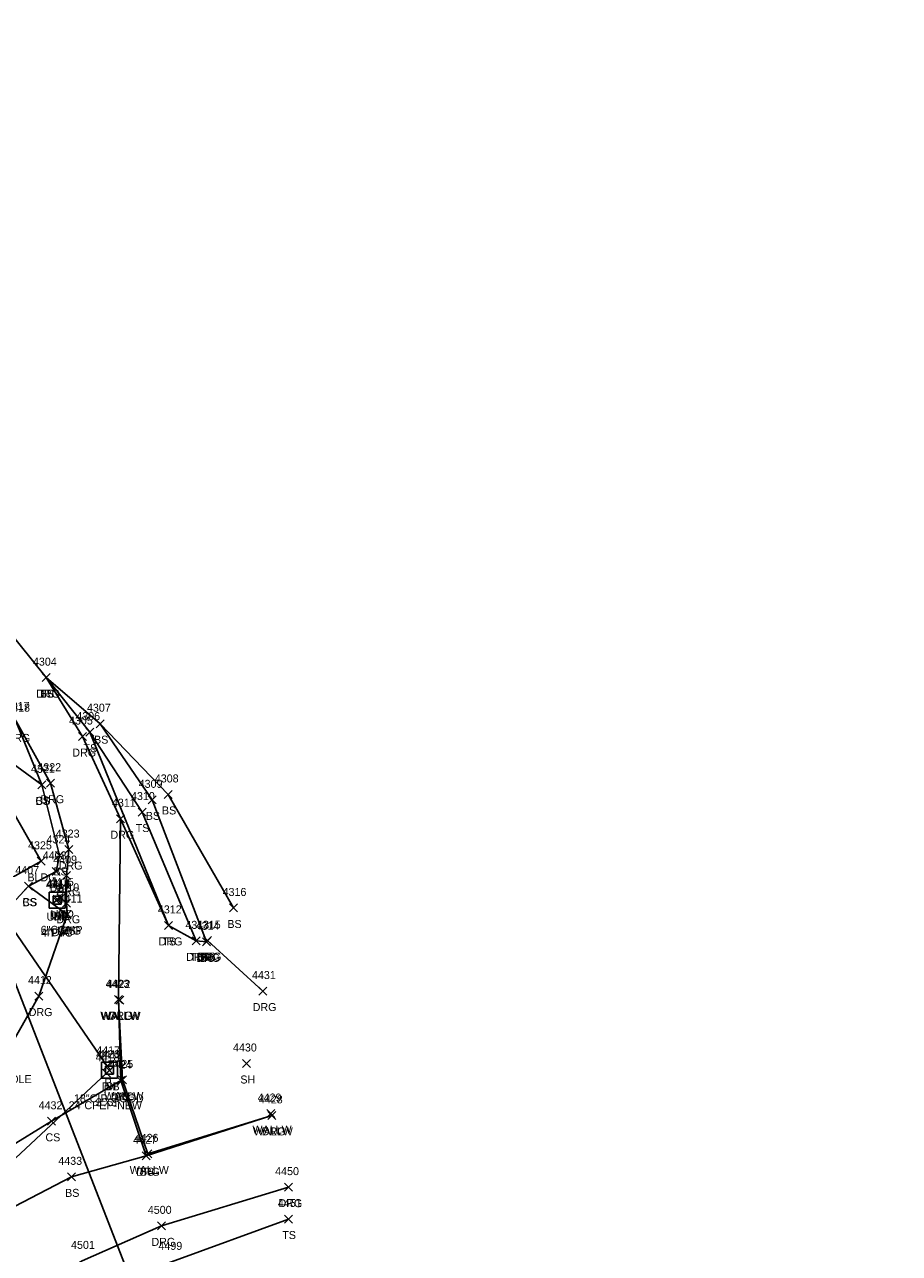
# Model space of a CAD drawing. Extents: x 49137 to 50946, y 9590 to 10709.
# Drawn here: x 50204 to 50422.7, y 10392.7 to 10699.8 of the extents above; entities that cross this region are included whole.
import ezdxf

# ---------------------------------------------------------------- set-up
doc = ezdxf.new("R2010")
doc.units = 0
for name, color, linetype in [('D_A', 7, 'Continuous'), ('D_C', 7, 'Continuous'), ('D_I', 7, 'Continuous'), ('D_TIC', 7, 'Continuous'), ('DCP', 7, 'Continuous'), ('DS', 7, 'Continuous'), ('L_A', 7, 'Continuous'), ('L_C', 7, 'Continuous'), ('L_I', 7, 'Continuous'), ('L_TIC', 7, 'Continuous'), ('LBC', 7, 'Continuous'), ('LELB', 7, 'Continuous'), ('LW', 7, 'Continuous'), ('R_A', 7, 'Continuous'), ('R_I', 7, 'Continuous'), ('R_TIC', 7, 'Continuous'), ('RDG', 7, 'Continuous')]:
    doc.layers.add(name, color=color, linetype=linetype)

msp = doc.modelspace()

# ---------------------------------------------------------------- linework, layer by layer
at = {"layer": 'D_TIC'}
for points in [[(50211.01, 10479.85), (50213.01, 10481.85)], [(50213.01, 10479.85), (50211.01, 10481.85)], [(50211.17, 10480.18), (50213.17, 10482.18)], [(50213.17, 10480.18), (50211.17, 10482.18)], [(50212.02, 10480.55), (50214.02, 10482.55)], [(50214.02, 10480.55), (50212.02, 10482.55)], [(50223.61, 10438.45), (50225.61, 10440.45)], [(50225.61, 10438.45), (50223.61, 10440.45)], [(50223.44, 10436.72), (50225.44, 10438.72)], [(50225.44, 10436.72), (50223.44, 10438.72)], [(50224.19, 10437.43), (50226.19, 10439.43)], [(50226.19, 10437.43), (50224.19, 10439.43)]]:
    msp.add_lwpolyline(points, dxfattribs=at)
at = {"layer": 'DCP'}
for points in [[(49941.69, 9827.48), (50059.34, 9808.37), (50181.4, 9733.09), (50281.74, 9743.29), (50422.72, 9892.52), (50122.34, 10663.61), (50179.93, 10552.61), (50179.64, 10394.45), (50122.34, 10285.07), (50121.56, 10284.35)], [(50173.14, 10514.39), (50224.61, 10439.45)], [(50224.44, 10437.72), (50180.22, 10396.54)]]:
    msp.add_lwpolyline(points, dxfattribs=at)
at = {"layer": 'DS'}
for p, q in [((50210.14, 10482.97), (50214.14, 10482.97)), ((50210.14, 10478.97), (50210.14, 10482.97)), ((50211.14, 10479.97), (50211.14, 10481.97)), ((50211.14, 10481.97), (50213.14, 10481.97)), ((50213.14, 10479.97), (50211.14, 10479.97)), ((50212.14, 10480.97), (50212.14, 10480.97)), ((50212.14, 10480.97), (50212.14, 10480.97)), ((50213.14, 10481.97), (50213.14, 10479.97)), ((50214.14, 10482.97), (50214.14, 10478.97)), ((50214.14, 10478.97), (50210.14, 10478.97)), ((50223.21, 10440.47), (50227.21, 10440.47)), ((50223.21, 10436.47), (50223.21, 10440.47)), ((50227.21, 10440.47), (50227.21, 10436.47)), ((50224.21, 10437.47), (50224.21, 10439.47)), ((50224.21, 10439.47), (50226.21, 10439.47)), ((50226.21, 10437.47), (50224.21, 10437.47)), ((50225.22, 10438.48), (50225.22, 10438.48)), ((50225.22, 10438.48), (50225.22, 10438.48)), ((50226.21, 10439.47), (50226.21, 10437.47)), ((50227.21, 10436.47), (50223.21, 10436.47))]:
    msp.add_line(p, q, dxfattribs=at)
at = {"layer": 'L_TIC'}
for points in [[(50208.41, 10535.57), (50210.41, 10537.57)], [(50210.41, 10535.57), (50208.41, 10537.57)], [(50208.41, 10535.57), (50210.41, 10537.57)], [(50210.41, 10535.57), (50208.41, 10537.57)], [(50221.92, 10524.07), (50223.92, 10526.07)], [(50223.92, 10524.07), (50221.92, 10526.07)], [(50221.92, 10524.07), (50223.92, 10526.07)], [(50223.92, 10524.07), (50221.92, 10526.07)], [(50219.31, 10521.95), (50221.31, 10523.95)], [(50221.31, 10521.95), (50219.31, 10523.95)], [(50219.31, 10521.95), (50221.31, 10523.95)], [(50221.31, 10521.95), (50219.31, 10523.95)], [(50207.27, 10508.79), (50209.27, 10510.79)], [(50209.27, 10508.79), (50207.27, 10510.79)], [(50207.27, 10508.79), (50209.27, 10510.79)], [(50209.27, 10508.79), (50207.27, 10510.79)], [(50238.89, 10506.39), (50240.89, 10508.39)], [(50240.89, 10506.39), (50238.89, 10508.39)], [(50234.85, 10505.04), (50236.85, 10507.04)], [(50236.85, 10505.04), (50234.85, 10507.04)], [(50232.37, 10501.99), (50234.37, 10503.99)], [(50234.37, 10501.99), (50232.37, 10503.99)], [(50211.74, 10491.15), (50213.74, 10493.15)], [(50213.74, 10491.15), (50211.74, 10493.15)], [(50207.1, 10489.68), (50209.1, 10491.68)], [(50209.1, 10489.68), (50207.1, 10491.68)], [(50207.1, 10489.68), (50209.1, 10491.68)], [(50209.1, 10489.68), (50207.1, 10491.68)], [(50210.87, 10487.15), (50212.87, 10489.15)], [(50212.87, 10487.15), (50210.87, 10489.15)], [(50210.87, 10487.15), (50212.87, 10489.15)], [(50212.87, 10487.15), (50210.87, 10489.15)], [(50204, 10483.47), (50206, 10485.47)], [(50206, 10483.47), (50204, 10485.47)], [(50204, 10483.47), (50206, 10485.47)], [(50206, 10483.47), (50204, 10485.47)], [(50255.24, 10478.02), (50257.24, 10480.02)], [(50257.24, 10478.02), (50255.24, 10480.02)], [(50213.66, 10476.36), (50215.66, 10478.36)], [(50215.66, 10476.36), (50213.66, 10478.36)], [(50239.01, 10473.66), (50241.01, 10475.66)], [(50241.01, 10473.66), (50239.01, 10475.66)], [(50245.88, 10469.8), (50247.88, 10471.8)], [(50247.88, 10469.8), (50245.88, 10471.8)], [(50248.46, 10469.56), (50250.46, 10471.56)], [(50250.46, 10469.56), (50248.46, 10471.56)], [(50248.76, 10469.86), (50250.76, 10471.86)], [(50250.76, 10469.86), (50248.76, 10471.86)], [(50226.51, 10455.11), (50228.51, 10457.11)], [(50228.51, 10455.11), (50226.51, 10457.11)], [(50226.77, 10455), (50228.77, 10457)], [(50228.77, 10455), (50226.77, 10457)], [(50258.44, 10439.16), (50260.44, 10441.16)], [(50260.44, 10439.16), (50258.44, 10441.16)], [(50227.46, 10435.05), (50229.46, 10437.05)], [(50229.46, 10435.05), (50227.46, 10437.05)], [(50227.06, 10434.89), (50229.06, 10436.89)], [(50229.06, 10434.89), (50227.06, 10436.89)], [(50264.54, 10426.65), (50266.54, 10428.65)], [(50266.54, 10426.65), (50264.54, 10428.65)], [(50264.83, 10426.19), (50266.83, 10428.19)], [(50266.83, 10426.19), (50264.83, 10428.19)], [(50209.76, 10424.71), (50211.76, 10426.71)], [(50211.76, 10424.71), (50209.76, 10426.71)], [(50233.83, 10416.58), (50235.83, 10418.58)], [(50235.83, 10416.58), (50233.83, 10418.58)], [(50233.37, 10416.11), (50235.37, 10418.11)], [(50235.37, 10416.11), (50233.37, 10418.11)], [(50214.68, 10410.83), (50216.68, 10412.83)], [(50216.68, 10410.83), (50214.68, 10412.83)], [(50269.01, 10400.29), (50271.01, 10402.29)], [(50271.01, 10400.29), (50269.01, 10402.29)]]:
    msp.add_lwpolyline(points, dxfattribs=at)
at = {"layer": 'LBC'}
for points in [[(50208.1, 10490.68), (50199.54, 10505.75), (50188.54, 10499.87), (50193.08, 10491.83), (50197.16, 10484.51)], [(50208.1, 10490.68), (50197.16, 10484.51)]]:
    msp.add_lwpolyline(points, dxfattribs=at)
at = {"layer": 'LELB'}
for points in [[(50121.04, 10673.8), (50125.72, 10663.25), (50118.76, 10654.2), (50121.52, 10635.5), (50130.84, 10628.15), (50141.37, 10625.76), (50142.8, 10621.81), (50131.45, 10616.61), (50128.86, 10614.81), (50135.94, 10599.09), (50146.92, 10581.6), (50169.4, 10551.93), (50172.24, 10543.56), (50191.94, 10521.73), (50208.27, 10509.79)], [(50121.52, 10635.5), (50126.1, 10622.98), (50139.03, 10624.1), (50139.75, 10622.38), (50131.45, 10616.61), (50139.21, 10602.48), (50154.46, 10587.74), (50176.56, 10559.26), (50177.99, 10558.38), (50179.93, 10552.61), (50184.02, 10545.02), (50202.08, 10525.08), (50208.27, 10509.79), (50212.74, 10492.15), (50211.87, 10488.15)], [(50209.41, 10536.57), (50220.31, 10522.95), (50240.01, 10474.66)], [(50209.41, 10536.57), (50222.92, 10525.07), (50239.89, 10507.39), (50256.24, 10479.02)], [(50220.31, 10522.95), (50233.37, 10502.99), (50246.88, 10470.8)], [(50222.92, 10525.07), (50235.85, 10506.04), (50249.46, 10470.56), (50249.76, 10470.86)], [(50193.08, 10491.83), (50184.77, 10485.47), (50176.86, 10484.26), (50163.55, 10486.17), (50159.26, 10479.24), (50156.56, 10465.2), (50172.98, 10448.23), (50182.56, 10448.61), (50194.13, 10450.62), (50200.1, 10459.65), (50198.7, 10477.72), (50205, 10484.47), (50211.87, 10488.15)], [(50205, 10484.47), (50214.66, 10477.36)], [(50228.06, 10435.89), (50210.76, 10425.71), (50188.5, 10412.1), (50178.8, 10406.39)], [(50234.37, 10417.11), (50215.68, 10411.83), (50195.33, 10401.24), (50187.41, 10396.19)], [(50270.01, 10401.29), (50240.73, 10390.59), (50219.39, 10384), (50208.28, 10377.18), (50194.78, 10363.54), (50184.26, 10345.55), (50178.27, 10336.12)]]:
    msp.add_lwpolyline(points, dxfattribs=at)
at = {"layer": 'LW'}
msp.add_lwpolyline([(50227.77, 10456), (50227.51, 10456.11), (50228.46, 10436.05), (50234.83, 10417.58), (50265.83, 10427.19), (50265.54, 10427.65)], dxfattribs=at)
at = {"layer": 'R_TIC'}
for points in [[(50208.41, 10535.57), (50210.41, 10537.57)], [(50210.41, 10535.57), (50208.41, 10537.57)], [(50217.43, 10520.85), (50219.43, 10522.85)], [(50219.43, 10520.85), (50217.43, 10522.85)], [(50209.44, 10509.19), (50211.44, 10511.19)], [(50211.44, 10509.19), (50209.44, 10511.19)], [(50226.96, 10500.32), (50228.96, 10502.32)], [(50228.96, 10500.32), (50226.96, 10502.32)], [(50226.96, 10500.32), (50228.96, 10502.32)], [(50228.96, 10500.32), (50226.96, 10502.32)], [(50214.05, 10492.61), (50216.05, 10494.61)], [(50216.05, 10492.61), (50214.05, 10494.61)], [(50213.49, 10486.12), (50215.49, 10488.12)], [(50215.49, 10486.12), (50213.49, 10488.12)], [(50213.47, 10479.19), (50215.47, 10481.19)], [(50215.47, 10479.19), (50213.47, 10481.19)], [(50213.66, 10476.36), (50215.66, 10478.36)], [(50215.66, 10476.36), (50213.66, 10478.36)], [(50239.01, 10473.66), (50241.01, 10475.66)], [(50241.01, 10473.66), (50239.01, 10475.66)], [(50245.88, 10469.8), (50247.88, 10471.8)], [(50247.88, 10469.8), (50245.88, 10471.8)], [(50248.46, 10469.56), (50250.46, 10471.56)], [(50250.46, 10469.56), (50248.46, 10471.56)], [(50248.76, 10469.86), (50250.76, 10471.86)], [(50250.76, 10469.86), (50248.76, 10471.86)], [(50262.53, 10457.26), (50264.53, 10459.26)], [(50264.53, 10457.26), (50262.53, 10459.26)], [(50206.53, 10456), (50208.53, 10458)], [(50208.53, 10456), (50206.53, 10458)], [(50206.53, 10456), (50208.53, 10458)], [(50208.53, 10456), (50206.53, 10458)], [(50226.51, 10455.11), (50228.51, 10457.11)], [(50228.51, 10455.11), (50226.51, 10457.11)], [(50227.06, 10434.89), (50229.06, 10436.89)], [(50229.06, 10434.89), (50227.06, 10436.89)], [(50264.83, 10426.19), (50266.83, 10428.19)], [(50266.83, 10426.19), (50264.83, 10428.19)], [(50233.37, 10416.11), (50235.37, 10418.11)], [(50235.37, 10416.11), (50233.37, 10418.11)], [(50268.98, 10408.26), (50270.98, 10410.26)], [(50270.98, 10408.26), (50268.98, 10410.26)], [(50237.23, 10398.59), (50239.23, 10400.59)], [(50239.23, 10398.59), (50237.23, 10400.59)]]:
    msp.add_lwpolyline(points, dxfattribs=at)
at = {"layer": 'RDG'}
for points in [[(50119.02, 10699.76), (50135.14, 10671.06), (50153.64, 10632.53), (50170.9, 10598.36), (50195.96, 10553.2), (50209.41, 10536.57), (50218.43, 10521.85), (50227.96, 10501.32), (50227.51, 10456.11), (50228.06, 10435.89), (50234.37, 10417.11), (50265.83, 10427.19)], [(50110.8, 10693.82), (50121.04, 10673.8), (50126.58, 10664.65), (50145.31, 10626.1), (50162.07, 10592.03), (50186.9, 10549.34), (50201.97, 10525.51), (50210.44, 10510.19), (50215.05, 10493.61), (50214.49, 10487.12), (50214.47, 10480.19), (50214.66, 10477.36), (50207.53, 10457)], [(50095.25, 10547.5), (50093.45, 10565.17), (50103.93, 10565.73), (50107.41, 10556.05), (50110.4, 10521.45), (50105.68, 10496.74), (50106.96, 10485.77), (50113.12, 10471.78), (50124.76, 10458.74), (50147.1, 10444.79), (50157.25, 10438.91), (50175.59, 10435.41), (50187.55, 10433.23), (50196.81, 10438.28), (50207.53, 10457)], [(50227.96, 10501.32), (50240.01, 10474.66), (50246.88, 10470.8), (50249.46, 10470.56), (50249.76, 10470.86), (50263.53, 10458.26)], [(50269.98, 10409.26), (50238.23, 10399.59), (50218.39, 10390.84), (50203.41, 10381.68), (50192.27, 10366.32), (50182.22, 10345.19), (50178.27, 10336.12), (50177.24, 10330.6), (50176.48, 10328.28)]]:
    msp.add_lwpolyline(points, dxfattribs=at)

# ---------------------------------------------------------------- texts
at = {"layer": 'D_A'}
for s, p in [('UND', (50209.48, 10475.85)), ('DIB', (50210.28, 10476.18)), ('UND', (50210.5, 10476.55)), ('DI', (50211.2, 10475.97)), ('DIB', (50223.29, 10433.43)), ('P', (50223.82, 10432.72)), ('P', (50223.99, 10434.45)), ('DI', (50224.27, 10433.48))]:
    msp.add_text(s, height=2, dxfattribs=at).set_placement(p)
at = {"layer": 'D_C'}
for s, p in [('6"CGMP', (50208.01, 10472.55)), ('4"PVC', (50208.08, 10471.85)), ("4'DIA", (50208.83, 10471.97)), ('18"CIP-GOOD', (50216.33, 10430.45)), ("3'X3'", (50221.82, 10429.48)), ('24"CPEP-NEW', (50215.02, 10428.72))]:
    msp.add_text(s, height=2, dxfattribs=at).set_placement(p)
at = {"layer": 'D_I'}
for s, p in [('4416', (50209.43, 10484.18)), ('4415', (50210.33, 10484.55)), ('4414', (50209.31, 10483.85)), ('4413', (50209.45, 10483.97)), ('4420', (50221.87, 10441.48)), ('4417', (50221.92, 10442.45)), ('4419', (50222.49, 10441.43)), ('4418', (50221.75, 10440.72))]:
    msp.add_text(s, height=2, dxfattribs=at).set_placement(p)
at = {"layer": 'L_A'}
for s, p in [('TS', (50207.82, 10531.57)), ('BS', (50207.85, 10531.57)), ('TS', (50218.72, 10517.95)), ('TS', (50218.72, 10517.95)), ('BS', (50221.36, 10520.07)), ('BS', (50221.36, 10520.07)), ('CS', (50206.71, 10504.79)), ('BS', (50206.71, 10504.79)), ('BS', (50234.29, 10501.04)), ('BS', (50238.33, 10502.39)), ('TS', (50231.78, 10497.99)), ('BS', (50211.18, 10487.15)), ('BLDG', (50204.7, 10485.68)), ('BLDG', (50204.7, 10485.68)), ('BS', (50210.31, 10483.15)), ('BS', (50210.31, 10483.15)), ('CS', (50203.44, 10479.47)), ('BS', (50203.44, 10479.47)), ('CS', (50213.1, 10472.36)), ('BS', (50254.69, 10474.02)), ('TS', (50238.42, 10469.66)), ('TS', (50245.29, 10465.8)), ('BS', (50248.21, 10465.86)), ('BS', (50247.9, 10465.56)), ('WALLW', (50222.93, 10451.11)), ('WALLW', (50223.18, 10451)), ('SH', (50257.93, 10435.16)), ('WALLW', (50223.88, 10431.05)), ('CS', (50226.5, 10430.89)), ('CS', (50209.21, 10420.71)), ('WALLW', (50260.95, 10422.65)), ('WALLW', (50261.24, 10422.19)), ('WALLW', (50230.25, 10412.58)), ('BS', (50232.82, 10412.11)), ('BS', (50214.12, 10406.83)), ('TS', (50268.42, 10396.29))]:
    msp.add_text(s, height=2, dxfattribs=at).set_placement(p)
at = {"layer": 'L_C'}
msp.add_text('4XCHAIR LIFT SUPPORT POLE', height=2, dxfattribs=at).set_placement((50166.37, 10435.25))
at = {"layer": 'L_I'}
for s, p in [('4304', (50206.08, 10539.57)), ('4304', (50206.08, 10539.57)), ('4317', (50199.28, 10528.51)), ('4318', (50199.39, 10528.08)), ('4307', (50219.58, 10528.07)), ('4307', (50219.58, 10528.07)), ('4306', (50216.92, 10525.95)), ('4306', (50216.92, 10525.95)), ('4321', (50205.58, 10512.79)), ('4321', (50205.58, 10512.79)), ('4309', (50232.51, 10509.04)), ('4308', (50236.55, 10510.39)), ('4310', (50230.6, 10505.99)), ('4325', (50204.85, 10493.68)), ('4325', (50204.85, 10493.68)), ('4324', (50209.48, 10495.15)), ('4408', (50208.53, 10491.15)), ('4408', (50208.53, 10491.15)), ('4407', (50201.66, 10487.47)), ('4407', (50201.66, 10487.47)), ('4316', (50253.5, 10482.02)), ('4411', (50212.54, 10480.36)), ('4312', (50237.32, 10477.66)), ('4313', (50244.19, 10473.8)), ('4314', (50246.77, 10473.56)), ('4315', (50247.07, 10473.86)), ('4423', (50224.25, 10459.11)), ('4422', (50224.51, 10459)), ('4430', (50256.1, 10443.16)), ('4424', (50224.8, 10438.89)), ('4425', (50225.2, 10439.05)), ('4429', (50262.27, 10430.65)), ('4428', (50262.57, 10430.19)), ('4432', (50207.5, 10428.71)), ('4427', (50231.12, 10420.11)), ('4426', (50231.52, 10420.58)), ('4433', (50212.42, 10414.83)), ('4451', (50267.32, 10404.29)), ('4499', (50237.46, 10393.59))]:
    msp.add_text(s, height=2, dxfattribs=at).set_placement(p)
at = {"layer": 'R_A'}
for p in [(50206.9, 10531.57), (50199.46, 10520.51), (50215.92, 10516.85), (50207.93, 10505.19), (50225.45, 10496.32), (50225.45, 10496.32), (50212.54, 10488.61), (50211.98, 10482.12), (50211.95, 10475.19), (50212.15, 10472.36), (50237.5, 10469.66), (50244.37, 10465.8), (50247.25, 10465.86), (50246.95, 10465.56), (50205.02, 10452), (50205.02, 10452), (50225, 10451.11), (50261.02, 10453.26), (50225.55, 10430.89), (50263.31, 10422.19), (50231.86, 10412.11), (50267.47, 10404.26), (50235.71, 10394.59)]:
    msp.add_text('DRG', height=2, dxfattribs=at).set_placement(p)
at = {"layer": 'R_I'}
for s, p in [('4304', (50206.08, 10539.57)), ('4317', (50199.28, 10528.51)), ('4305', (50215.1, 10524.85)), ('4322', (50207.18, 10513.19)), ('4311', (50225.83, 10504.32)), ('4311', (50225.83, 10504.32)), ('4323', (50211.79, 10496.61)), ('4409', (50211.15, 10490.12)), ('4410', (50211.69, 10483.19)), ('4411', (50212.54, 10480.36)), ('4312', (50237.32, 10477.66)), ('4313', (50244.19, 10473.8)), ('4314', (50246.77, 10473.56)), ('4315', (50247.07, 10473.86)), ('4412', (50204.84, 10460)), ('4412', (50204.84, 10460)), ('4431', (50260.84, 10461.26)), ('4423', (50224.25, 10459.11)), ('4424', (50224.8, 10438.89)), ('4428', (50262.57, 10430.19)), ('4427', (50231.12, 10420.11)), ('4450', (50266.64, 10412.26)), ('4500', (50234.8, 10402.59)), ('4501', (50215.61, 10393.84))]:
    msp.add_text(s, height=2, dxfattribs=at).set_placement(p)

doc.saveas('drawing.dxf')
